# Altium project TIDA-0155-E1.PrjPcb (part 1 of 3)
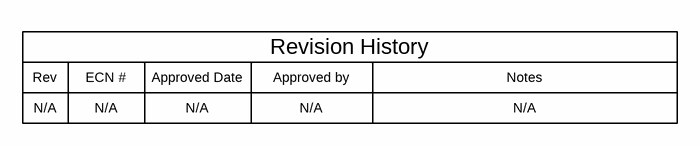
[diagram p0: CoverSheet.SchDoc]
CopyrightYear: 2017; PCB_Layout: Prasanna Rajagopal; PCB_Rev: E1; PRJ_Customer: Public Release; PRJ_Engineer: Prasanna Rajagopal; PRJ_Number: TIDA-01555; PRJ_Title: Enhanced Interface Reference Design to Connect Multiple ADCs to Processor for Input Expansion (48ch); SCH_Rev: E1; TechSupport: http://www.ti.com/support; TID: 01555
10 sheets, 765 parts. Net scope: global (net labels, ports and power ports of the same name join across sheets).
Board file: PCB.PcbDoc
Sheets:
  CoverSheet.SchDoc
  BlankSheet.SchDoc
  EVM_Hardware.SchDoc
  Page1.SchDoc
  Page2.SchDoc
  Page3.SchDoc
  Page4.SchDoc
  Page5.SchDoc
  Page6.SchDoc
  Paget2.SchDoc

## Sheet CoverSheet.SchDoc
size 431 x 279 mm; Date: Not shown in title block; ApprovedBy: Not shown in title block; CheckedBy: Not shown in title block; Author: Not shown in title block; CompanyName: Not shown in title block; Engineer: Not shown in title block; Organization: Not shown in title block; Address1: Not shown in title block; Address2: Not shown in title block; Address3: Not shown in title block; Address4: Not shown in title block; DocumentNumber: 1; Revision: Use project parameter SCH_Rev; SheetNumber: 1; SheetTotal: 3; PageSetup: Record=PageOptions¦CenterHorizontal=True¦CenterVertical=True¦PrintScale=1.00¦XCorrection=1.00¦YCorrection=1.00¦PrintKind=0¦BorderSize=5000000¦LeftOffset=0¦BottomOffset=0¦Orientation=2¦PaperLength=1000¦PaperWidth=1000¦Scale=100¦PaperSource=15¦PrintQuality=600¦MediaType=1¦DitherType=10¦PaperKind=Letter¦PrintScaleMode=1

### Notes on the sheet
- Rev
- N/A
- ECN #
- Approved Date
- Approved by
- Revision History
- Notes

## Sheet BlankSheet.SchDoc
size 431 x 279 mm; Date: Not shown in title block; ApprovedBy: Not shown in title block; CheckedBy: Not shown in title block; Author: Not shown in title block; CompanyName: Not shown in title block; Engineer: Not shown in title block; Organization: Not shown in title block; Address1: Not shown in title block; Address2: Not shown in title block; Address3: Not shown in title block; Address4: Not shown in title block; DocumentNumber: 1; Revision: Use project parameter SCH_Rev; SheetNumber: 2; SheetTotal: 3; PageSetup: Record=PageOptions¦CenterHorizontal=True¦CenterVertical=True¦PrintScale=1.00¦XCorrection=1.00¦YCorrection=1.00¦PrintKind=0¦BorderSize=5000000¦LeftOffset=0¦BottomOffset=0¦Orientation=2¦PaperLength=1000¦PaperWidth=1000¦Scale=100¦PaperSource=15¦PrintQuality=600¦MediaType=1¦DitherType=10¦PaperKind=Letter¦PrintScaleMode=1

## Sheet EVM_Hardware.SchDoc
size 431 x 279 mm; Date: Not shown in title block; ApprovedBy: Not shown in title block; CheckedBy: Not shown in title block; Author: Not shown in title block; CompanyName: Not shown in title block; Engineer: Not shown in title block; Organization: Not shown in title block; Address1: Not shown in title block; Address2: Not shown in title block; Address3: Not shown in title block; Address4: Not shown in title block; DocumentNumber: 1; Revision: Use project parameter SCH_Rev; SheetNumber: 3; SheetTotal: 3; PageSetup: Record=PageOptions¦CenterHorizontal=True¦CenterVertical=True¦PrintScale=1.00¦XCorrection=1.00¦YCorrection=1.00¦PrintKind=0¦BorderSize=5000000¦LeftOffset=0¦BottomOffset=0¦Orientation=2¦PaperLength=1000¦PaperWidth=1000¦Scale=100¦PaperSource=15¦PrintQuality=600¦MediaType=1¦DitherType=10¦PaperKind=Letter¦PrintScaleMode=1
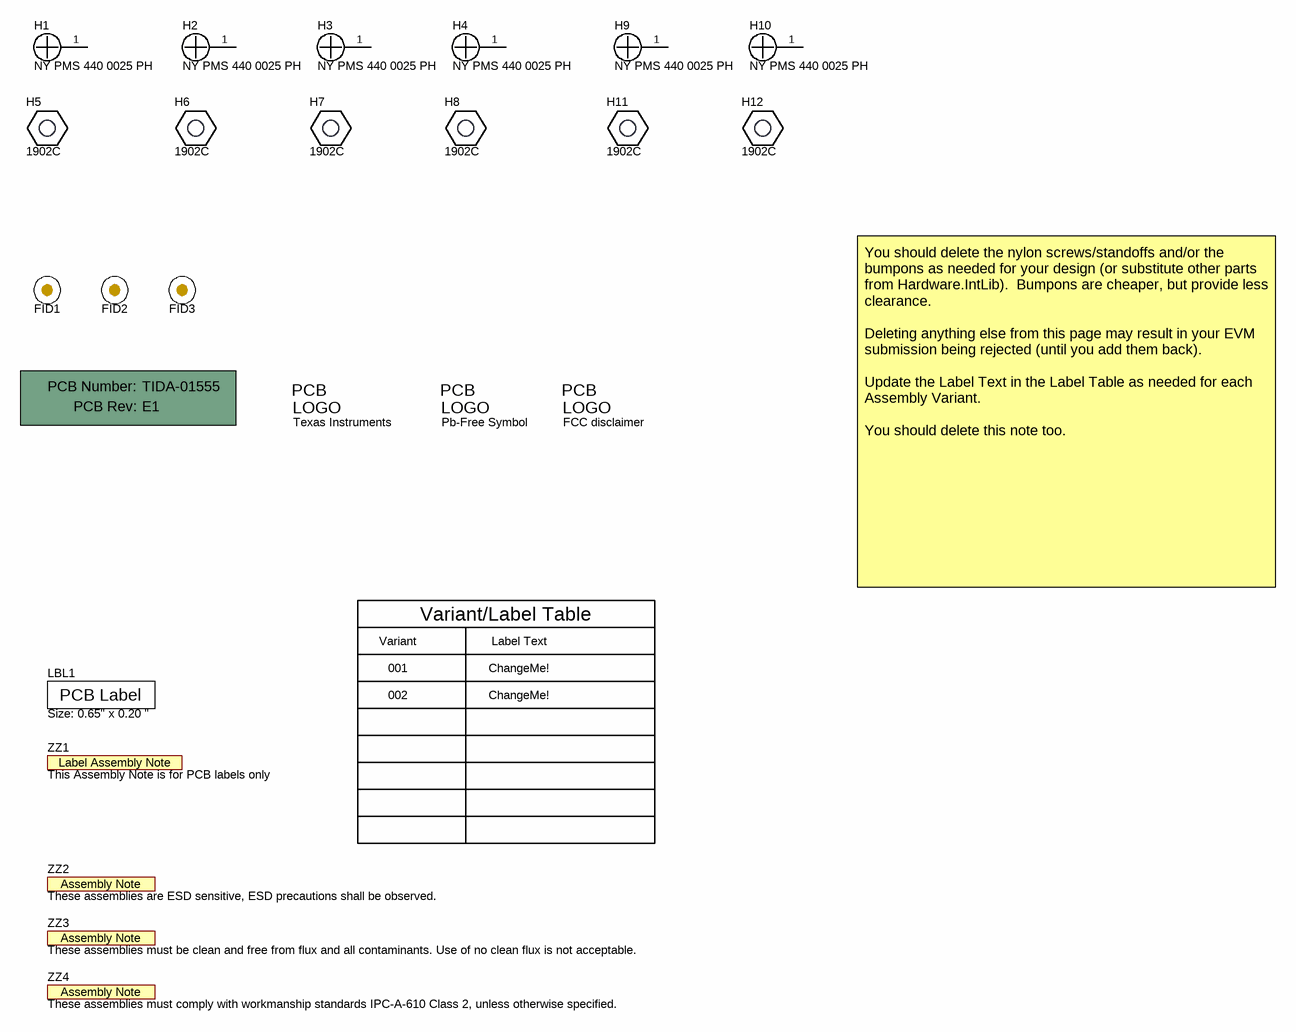
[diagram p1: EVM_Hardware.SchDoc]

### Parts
!PCB1  Printed Circuit Board  (value not drawn)  (mechanical)
FID1  Fiducial  [Fiducial10-20]  (value not drawn)
FID2  Fiducial  [Fiducial10-20]  (value not drawn)
FID3  Fiducial  [Fiducial10-20]  (value not drawn)
H1  NY PMS 440 0025 PH  [NY PMS 440 0025 PH]
H2  NY PMS 440 0025 PH  [NY PMS 440 0025 PH]
H3  NY PMS 440 0025 PH  [NY PMS 440 0025 PH]
H4  NY PMS 440 0025 PH  [NY PMS 440 0025 PH]
H5  1902C  [Keystone_1902C]
H6  1902C  [Keystone_1902C]
H7  1902C  [Keystone_1902C]
H8  1902C  [Keystone_1902C]
H9  NY PMS 440 0025 PH  [NY PMS 440 0025 PH]
H10  NY PMS 440 0025 PH  [NY PMS 440 0025 PH]
H11  1902C  [Keystone_1902C]
H12  1902C  [Keystone_1902C]
LBL1  Size: 0.65" x 0.20 "  [Label_650x200]
Logo1  Texas Instruments  [TI_Stacked_Overlay_Small]  (no BOM)
Logo2  Pb-Free Symbol  [Pb-Free_Overlay_Small]  (no BOM)
Logo3  FCC disclaimer  [FCC_disclaimer]  (no BOM)
ZZ1  This Assembly Note is for PCB labels only  [AssemblyNoteLabel]  (no BOM)
ZZ2  These assemblies are ESD sensitive, ESD precautions shall be observed.  [AssemblyNote]  (no BOM)
ZZ3  These assemblies must be clean and free from flux and all contaminants. Use of no clean flux is not acceptable.  [AssemblyNote]  (no BOM)
ZZ4  These assemblies must comply with workmanship standards IPC-A-610 Class 2, unless otherwise specified.  [AssemblyNote]  (no BOM)

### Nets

Not connected (* = marked no-connect by the designer): H1 1; H2 1; H3 1; H4 1; H9 1; H10 1

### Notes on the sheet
- Variant
- Variant/Label Table
- Label Text
- You should delete the nylon screws/standoffs and/or the bumpons as needed for your design (or substitute other parts from Hardware.IntLib).  Bumpons are cheaper, but provide less clearance.
  Deleting anything else from this page may result in your EVM submission being rejected (until you add them back).
  Update the Label Text in the Label Table as needed for each Assembly Variant.
  You should delete this note too.
- 001
- 002
- ChangeMe!

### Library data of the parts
!PCB1 = PCB: Manufacturer: Any; PartNumber: TIDA-01555; SymbolCreator: a0412235
FID1-FID3 = Fiducial: Fiducial mark.  There is nothing to buy or mount.; SymbolCreator: codlsc
H1-H4 H9 H10 = NY PMS 440 0025 PH: Machine Screw, Round, #4-40 x 1/4, Nylon, Philips panhead; Manufacturer: B&F Fastener Supply; CompType: Hardware; SymbolCreator: codlsc; U/M: EA
H5-H8 H11 H12 = 1902C: Standoff, Hex, 0.5"L #4-40 Nylon; Manufacturer: Keystone; CompType: Hardware
LBL1 = THT-14-423-10: Thermal Transfer Printable Labels, 0.650" W x 0.200" H - 10,000 per roll; Manufacturer: Brady; SymbolCreator: a0412235; CompType: Label
Logo1 = TI_Logo: Texas Instrument Corporate Signature; SymbolCreator: codlsc
Logo2 = Pb-Free: SymbolCreator: a0412235
Logo3 = FCC_disclaimer: SymbolCreator: codlsc
ZZ1 = AssemblyNoteLabel: SymbolCreator: a0412235
ZZ2-ZZ4 = AssemblyNote: SymbolCreator: codlsc

## Sheet Page1.SchDoc
size 431 x 279 mm; Date: Not shown in title block; ApprovedBy: Not shown in title block; CheckedBy: Not shown in title block; Author: Not shown in title block; CompanyName: Not shown in title block; Engineer: Not shown in title block; Organization: Not shown in title block; Address1: Not shown in title block; Address2: Not shown in title block; Address3: Not shown in title block; Address4: Not shown in title block; DocumentNumber: 1; Revision: Use project parameter SCH_Rev; SheetNumber: 2; SheetTotal: 3; PageSetup: Record=PageOptions¦CenterHorizontal=True¦CenterVertical=True¦PrintScale=1.00¦XCorrection=1.00¦YCorrection=1.00¦PrintKind=0¦BorderSize=5000000¦LeftOffset=0¦BottomOffset=0¦Orientation=2¦PaperLength=1000¦PaperWidth=1000¦Scale=100¦PaperSource=15¦PrintQuality=600¦MediaType=1¦DitherType=10¦PaperKind=Letter¦PrintScaleMode=1
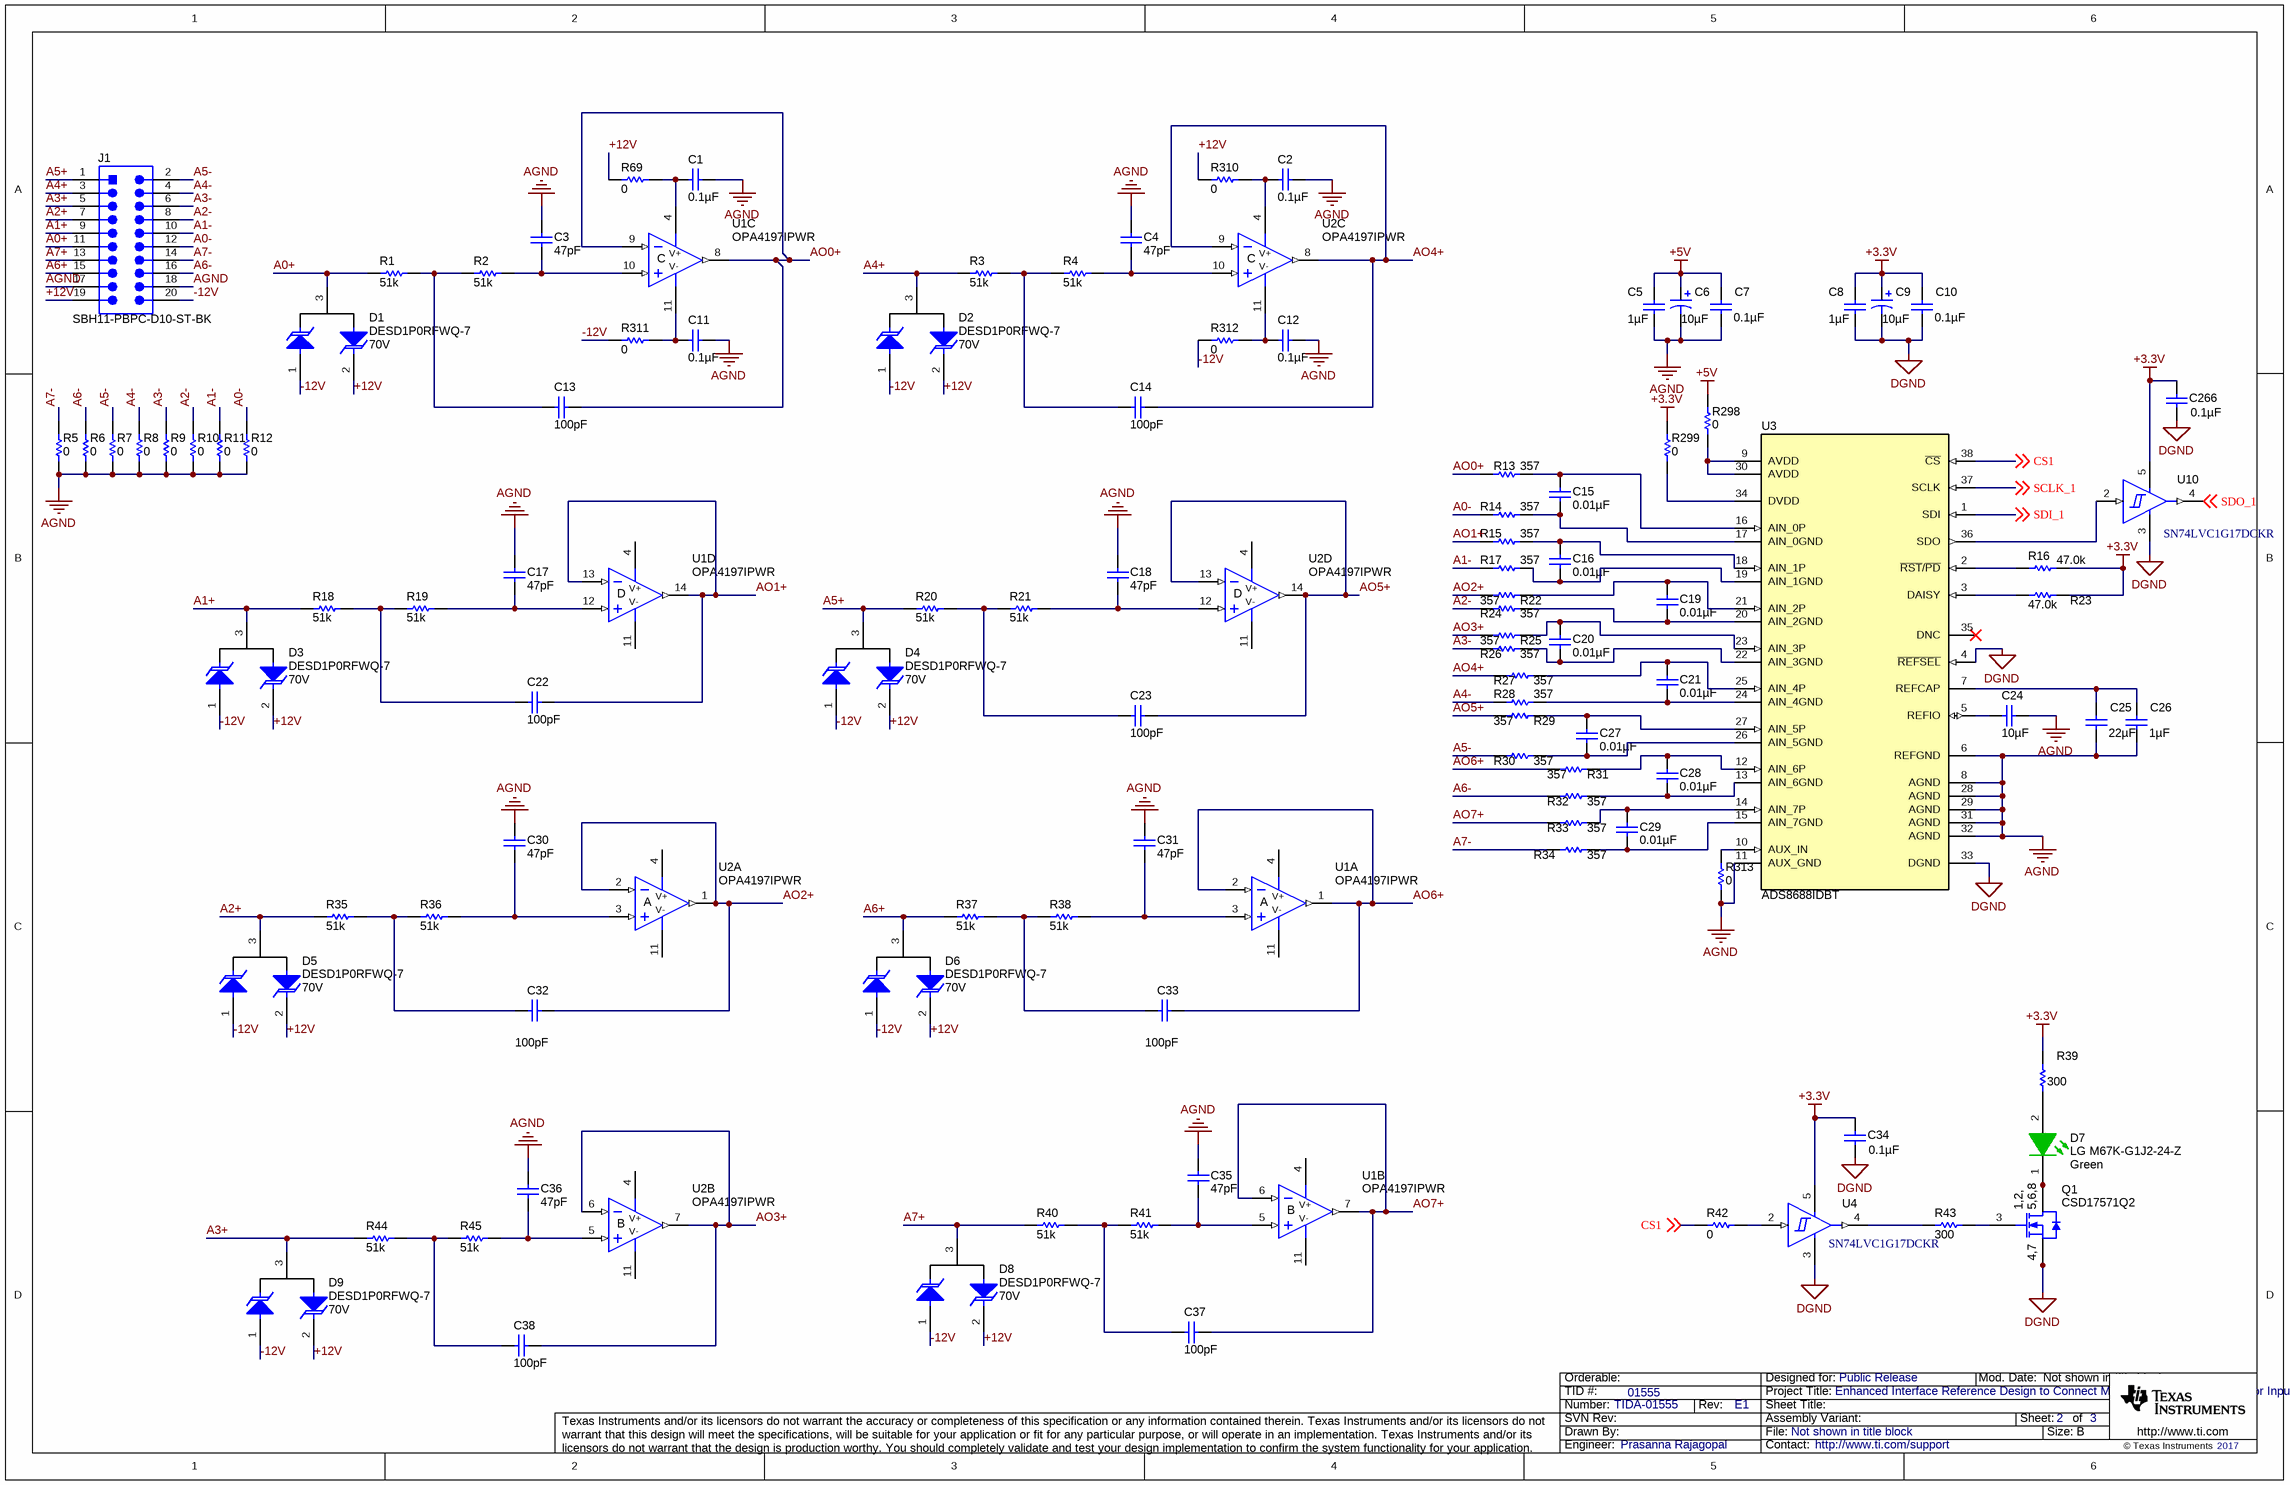
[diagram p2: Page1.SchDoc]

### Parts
C1  ValueDisplayed: 0.1µF  [0603]  (hidden comment: 06035C104KAT2A)
C2  ValueDisplayed: 0.1µF  [0603]  (hidden comment: 06035C104KAT2A)
C3  ValueDisplayed: 47pF  [0603]  (hidden comment: C0603C470J5GACTU)
C4  ValueDisplayed: 47pF  [0603]  (hidden comment: C0603C470J5GACTU)
C5  ValueDisplayed: 1µF  [0805_HV]  (hidden comment: LMK212B7105KD-T)
C6  ValueDisplayed: 10µF  [3216-18]  (hidden comment: TAJA106M010RNJ)
C7  ValueDisplayed: 0.1µF  [0402]  (hidden comment: C1005X5R1A104K050BA)
C8  ValueDisplayed: 1µF  [0805_HV]  (hidden comment: LMK212B7105KD-T)
C9  ValueDisplayed: 10µF  [3216-18]  (hidden comment: TAJA106M010RNJ)
C10  ValueDisplayed: 0.1µF  [0402]  (hidden comment: C1005X5R1A104K050BA)
C11  ValueDisplayed: 0.1µF  [0603]  (hidden comment: 06035C104KAT2A)
C12  ValueDisplayed: 0.1µF  [0603]  (hidden comment: 06035C104KAT2A)
C13  ValueDisplayed: 100pF  [0603]  (hidden comment: 06035A101FAT2A)
C14  ValueDisplayed: 100pF  [0603]  (hidden comment: 06035A101FAT2A)
C15  ValueDisplayed: 0.01µF  [0603]  (hidden comment: C1608X7R1H103K080AA)
C16  ValueDisplayed: 0.01µF  [0603]  (hidden comment: C1608X7R1H103K080AA)
C17  ValueDisplayed: 47pF  [0603]  (hidden comment: C0603C470J5GACTU)
C18  ValueDisplayed: 47pF  [0603]  (hidden comment: C0603C470J5GACTU)
C19  ValueDisplayed: 0.01µF  [0603]  (hidden comment: C1608X7R1H103K080AA)
C20  ValueDisplayed: 0.01µF  [0603]  (hidden comment: C1608X7R1H103K080AA)
C21  ValueDisplayed: 0.01µF  [0603]  (hidden comment: C1608X7R1H103K080AA)
C22  ValueDisplayed: 100pF  [0603]  (hidden comment: 06035A101FAT2A)
C23  ValueDisplayed: 100pF  [0603]  (hidden comment: 06035A101FAT2A)
C24  ValueDisplayed: 10µF  [0805_HV]  (hidden comment: GRM21BR71A106KE51L)
C25  ValueDisplayed: 22µF  [1210_280]  (hidden comment: C3225X7R1C226K250AC)
C26  ValueDisplayed: 1µF  [0603]  (hidden comment: C1608X7R1C105K080AC)
C27  ValueDisplayed: 0.01µF  [0603]  (hidden comment: C1608X7R1H103K080AA)
C28  ValueDisplayed: 0.01µF  [0603]  (hidden comment: C1608X7R1H103K080AA)
C29  ValueDisplayed: 0.01µF  [0603]  (hidden comment: C1608X7R1H103K080AA)
C30  ValueDisplayed: 47pF  [0603]  (hidden comment: C0603C470J5GACTU)
C31  ValueDisplayed: 47pF  [0603]  (hidden comment: C0603C470J5GACTU)
C32  ValueDisplayed: 100pF  [0603]  (hidden comment: 06035A101FAT2A)
C33  ValueDisplayed: 100pF  [0603]  (hidden comment: 06035A101FAT2A)
C34  ValueDisplayed: 0.1µF  [0603]  (hidden comment: GRM188R71C104KA01D)
C35  ValueDisplayed: 47pF  [0603]  (hidden comment: C0603C470J5GACTU)
C36  ValueDisplayed: 47pF  [0603]  (hidden comment: C0603C470J5GACTU)
C37  ValueDisplayed: 100pF  [0603]  (hidden comment: 06035A101FAT2A)
C38  ValueDisplayed: 100pF  [0603]  (hidden comment: 06035A101FAT2A)
C266  ValueDisplayed: 0.1µF  [0603]  (hidden comment: GRM188R71C104KA01D)
D1  DESD1P0RFWQ-7  value 70V  [SOT-323]
D2  DESD1P0RFWQ-7  value 70V  [SOT-323]
D3  DESD1P0RFWQ-7  value 70V  [SOT-323]
D4  DESD1P0RFWQ-7  value 70V  [SOT-323]
D5  DESD1P0RFWQ-7  value 70V  [SOT-323]
D6  DESD1P0RFWQ-7  value 70V  [SOT-323]
D7  LG M67K-G1J2-24-Z  value Green  [LG_M67K_Green]
D8  DESD1P0RFWQ-7  value 70V  [SOT-323]
D9  DESD1P0RFWQ-7  value 70V  [SOT-323]
J1  SBH11-PBPC-D10-ST-BK  [Sullins_SBH11-xxxC-D10-ST]
Q1  CSD17571Q2  [DQK0006C]
R1  ValueDisplayed: 51k  [0603]  (hidden comment: CRCW060351K0JNEA)
R2  ValueDisplayed: 51k  [0603]  (hidden comment: CRCW060351K0JNEA)
R3  ValueDisplayed: 51k  [0603]  (hidden comment: CRCW060351K0JNEA)
R4  ValueDisplayed: 51k  [0603]  (hidden comment: CRCW060351K0JNEA)
R5  ValueDisplayed: 0  [0603]  (hidden comment: CRCW06030000Z0EA)
R6  ValueDisplayed: 0  [0603]  (hidden comment: CRCW06030000Z0EA)
R7  ValueDisplayed: 0  [0603]  (hidden comment: CRCW06030000Z0EA)
R8  ValueDisplayed: 0  [0603]  (hidden comment: CRCW06030000Z0EA)
R9  ValueDisplayed: 0  [0603]  (hidden comment: CRCW06030000Z0EA)
R10  ValueDisplayed: 0  [0603]  (hidden comment: CRCW06030000Z0EA)
R11  ValueDisplayed: 0  [0603]  (hidden comment: CRCW06030000Z0EA)
R12  ValueDisplayed: 0  [0603]  (hidden comment: CRCW06030000Z0EA)
R13  ValueDisplayed: 357  [0402]  (hidden comment: CRCW0402357RFKED)
R14  ValueDisplayed: 357  [0402]  (hidden comment: CRCW0402357RFKED)
R15  ValueDisplayed: 357  [0402]  (hidden comment: CRCW0402357RFKED)
R16  ValueDisplayed: 47.0k  [0603]  (hidden comment: RC0603FR-0747KL)
R17  ValueDisplayed: 357  [0402]  (hidden comment: CRCW0402357RFKED)
R18  ValueDisplayed: 51k  [0603]  (hidden comment: CRCW060351K0JNEA)
R19  ValueDisplayed: 51k  [0603]  (hidden comment: CRCW060351K0JNEA)
R20  ValueDisplayed: 51k  [0603]  (hidden comment: CRCW060351K0JNEA)
R21  ValueDisplayed: 51k  [0603]  (hidden comment: CRCW060351K0JNEA)
R22  ValueDisplayed: 357  [0402]  (hidden comment: CRCW0402357RFKED)
R23  ValueDisplayed: 47.0k  [0603]  (hidden comment: RC0603FR-0747KL)
R24  ValueDisplayed: 357  [0402]  (hidden comment: CRCW0402357RFKED)
R25  ValueDisplayed: 357  [0402]  (hidden comment: CRCW0402357RFKED)
R26  ValueDisplayed: 357  [0402]  (hidden comment: CRCW0402357RFKED)
R27  ValueDisplayed: 357  [0402]  (hidden comment: CRCW0402357RFKED)
R28  ValueDisplayed: 357  [0402]  (hidden comment: CRCW0402357RFKED)
R29  ValueDisplayed: 357  [0402]  (hidden comment: CRCW0402357RFKED)
R30  ValueDisplayed: 357  [0402]  (hidden comment: CRCW0402357RFKED)
R31  ValueDisplayed: 357  [0402]  (hidden comment: CRCW0402357RFKED)
R32  ValueDisplayed: 357  [0402]  (hidden comment: CRCW0402357RFKED)
R33  ValueDisplayed: 357  [0402]  (hidden comment: CRCW0402357RFKED)
R34  ValueDisplayed: 357  [0402]  (hidden comment: CRCW0402357RFKED)
R35  ValueDisplayed: 51k  [0603]  (hidden comment: CRCW060351K0JNEA)
R36  ValueDisplayed: 51k  [0603]  (hidden comment: CRCW060351K0JNEA)
R37  ValueDisplayed: 51k  [0603]  (hidden comment: CRCW060351K0JNEA)
R38  ValueDisplayed: 51k  [0603]  (hidden comment: CRCW060351K0JNEA)
R39  ValueDisplayed: 300  [0603]  (hidden comment: CRCW0603300RJNEA)
R40  ValueDisplayed: 51k  [0603]  (hidden comment: CRCW060351K0JNEA)
R41  ValueDisplayed: 51k  [0603]  (hidden comment: CRCW060351K0JNEA)
R42  ValueDisplayed: 0  [0603]  (hidden comment: RMCF0603ZT0R00)
R43  ValueDisplayed: 300  [0603]  (hidden comment: CRCW0603300RJNEA)
R44  ValueDisplayed: 51k  [0603]  (hidden comment: CRCW060351K0JNEA)
R45  ValueDisplayed: 51k  [0603]  (hidden comment: CRCW060351K0JNEA)
R69  ValueDisplayed: 0  [0402]  (hidden comment: CRCW04020000Z0ED)
R298  ValueDisplayed: 0  [0603]  (hidden comment: CRCW06030000Z0EA)
R299  ValueDisplayed: 0  [0603]  (hidden comment: CRCW06030000Z0EA)
R310  ValueDisplayed: 0  [0402]  (hidden comment: CRCW04020000Z0ED)
R311  ValueDisplayed: 0  [0402]  (hidden comment: CRCW04020000Z0ED)
R312  ValueDisplayed: 0  [0402]  (hidden comment: CRCW04020000Z0ED)
R313  ValueDisplayed: 0  [0402]  (hidden comment: CRCW04020000Z0ED)
U1  OPA4197IPWR  [PW0014A_N]  (parts A,B,C,D of 4)
U2  OPA4197IPWR  [PW0014A_N]  (parts A,B,C,D of 4)
U3  ADS8688IDBT  [DBT0038A_N]
U4  SN74LVC1G17DCKR  [DCK0005A_N]
U10  SN74LVC1G17DCKR  [DCK0005A_N]

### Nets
+3.3V: C8.1 C9.1(+) C10.1 C34.1 C266.1 R16.2 R23.2 R39.2 R299.2 U4.5(VCC) U10.5(VCC)
+5V: C5.1 C6.1(+) C7.1 R298.2
+12V: D1.2(C) D2.2(C) D3.2(C) D4.2(C) D5.2(C) D6.2(C) D8.2(C) D9.2(C) J1.19 R69.1 R310.1
-12V: D1.1(A) D2.1(A) D3.1(A) D4.1(A) D5.1(A) D6.1(A) D8.1(A) D9.1(A) J1.20 R311.1 R312.1
AGND: C1.1 C2.1 C3.1 C4.1 C5.2 C6.2(-) C7.2 C11.1 C12.1 C17.1 C18.1 C24.2 C25.2 C26.2 C30.1 C31.1 C35.1 C36.1 J1.17 J1.18 R5.1 R6.1 R7.1 R8.1 R9.1 R10.1 R11.1 R12.1 R313.1 U3.6(REFGND) U3.8(AGND) U3.11(AUX_GND) U3.28(AGND) U3.29(AGND) U3.31(AGND) U3.32(AGND)
DGND: C8.2 C9.2(-) C10.2 C34.2 C266.2 Q1.4(S) Q1.7(S) U3.4(~{REFSEL}) U3.33(DGND) U4.3(GND) U10.3(GND)
A0+: D1.3(C) J1.11 R1.1
A0-: J1.12 R12.2 R14.1
A1+: D3.3(C) J1.9 R18.1
A1-: J1.10 R11.2 R17.1
A2+: D5.3(C) J1.7 R35.1
A2-: J1.8 R10.2 R24.1
A3+: D9.3(C) J1.5 R44.1
A3-: J1.6 R9.2 R26.1
A4+: D2.3(C) J1.3 R3.1
A4-: J1.4 R8.2 R28.1
A5+: D4.3(C) J1.1 R20.1
A5-: J1.2 R7.2 R30.1
A6+: D6.3(C) J1.15 R37.1
A6-: J1.16 R6.2 R32.1
A7+: D8.3(C) J1.13 R40.1
A7-: J1.14 R5.2 R34.1
AO0+: C13.1 R13.1 U1.8(OUT) U1.9(IN-)
AO1+: C22.1 R15.1 U1.13(IN-) U1.14(OUT)
AO2+: C32.1 R22.1 U2.1(OUT) U2.2(IN-)
AO3+: C38.1 R25.1 U2.6(IN-) U2.7(OUT)
AO4+: C14.1 R27.1 U2.8(OUT) U2.9(IN-)
AO5+: C23.1 R29.1 U2.13(IN-) U2.14(OUT)
AO6+: C33.1 R31.1 U1.1(OUT) U1.2(IN-)
AO7+: C37.1 R33.1 U1.6(IN-) U1.7(OUT)
CS1: R42.1 U3.38(~{CS}) ; off-sheet CS1
SCLK_1: U3.37(SCLK) ; off-sheet SCLK_1
SDI_1: U3.1(SDI) ; off-sheet SDI_1
SDO_1: U10.4(Y) ; off-sheet SDO_1
NetC1_2: C1.2 R69.2 U1.4(V+)
NetC2_2: C2.2 R310.2 U2.4(V+)
NetC3_2: C3.2 R2.2 U1.10(IN+)
NetC4_2: C4.2 R4.2 U2.10(IN+)
NetC11_2: C11.2 R311.2 U1.11(V-)
NetC12_2: C12.2 R312.2 U2.11(V-)
NetC13_2: C13.2 R1.2 R2.1
NetC14_2: C14.2 R3.2 R4.1
NetC15_1: C15.1 R13.2 U3.16(AIN_0P)
NetC15_2: C15.2 R14.2 U3.17(AIN_0GND)
NetC16_1: C16.1 R15.2 U3.18(AIN_1P)
NetC16_2: C16.2 R17.2 U3.19(AIN_1GND)
NetC17_2: C17.2 R19.2 U1.12(IN+)
NetC18_2: C18.2 R21.2 U2.12(IN+)
NetC19_1: C19.1 R22.2 U3.21(AIN_2P)
NetC19_2: C19.2 R24.2 U3.20(AIN_2GND)
NetC20_1: C20.1 R25.2 U3.23(AIN_3P)
NetC20_2: C20.2 R26.2 U3.22(AIN_3GND)
NetC21_1: C21.1 R27.2 U3.25(AIN_4P)
NetC21_2: C21.2 R28.2 U3.24(AIN_4GND)
NetC22_2: C22.2 R18.2 R19.1
NetC23_2: C23.2 R20.2 R21.1
NetC24_1: C24.1 U3.5(REFIO)
NetC25_1: C25.1 C26.1 U3.7(REFCAP)
NetC27_1: C27.1 R29.2 U3.27(AIN_5P)
NetC27_2: C27.2 R30.2 U3.26(AIN_5GND)
NetC28_1: C28.1 R31.2 U3.12(AIN_6P)
NetC28_2: C28.2 R32.2 U3.13(AIN_6GND)
NetC29_1: C29.1 R33.2 U3.14(AIN_7P)
NetC29_2: C29.2 R34.2 U3.15(AIN_7GND)
NetC30_2: C30.2 R36.2 U2.3(IN+)
NetC31_2: C31.2 R38.2 U1.3(IN+)
NetC32_2: C32.2 R35.2 R36.1
NetC33_2: C33.2 R37.2 R38.1
NetC35_2: C35.2 R41.2 U1.5(IN+)
NetC36_2: C36.2 R45.2 U2.5(IN+)
NetC37_2: C37.2 R40.2 R41.1
NetC38_2: C38.2 R44.2 R45.1
NetD7_1: D7.1(K) Q1.1(D) Q1.2(D) Q1.5(D) Q1.6(D) Q1.8(D)
NetD7_2: D7.2(A) R39.1
NetQ1_3: Q1.3(G) R43.1
NetR16_1: R16.1 U3.2(~{RST}/~{PD})
NetR23_1: R23.1 U3.3(DAISY)
NetR42_2: R42.2 U4.2(A)
NetR43_2: R43.2 U4.4(Y)
NetR298_1: R298.1 U3.9(AVDD) U3.30(AVDD)
NetR299_1: R299.1 U3.34(DVDD)
NetR313_2: R313.2 U3.10(AUX_IN)
NetU3_36: U3.36(SDO) U10.2(A)

Not connected (* = marked no-connect by the designer): U3 35(DNC)*

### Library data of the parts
C1 C2 C11 C12 = 06035C104KAT2A: CAP, CERM, 0.1 µF, 50 V,+/- 10%, X7R, 0603; Manufacturer: AVX; Polarized: N; CompType: Capacitor; Value: 0.1uF; U/M: EA; Cap_F: 0.0000001; Tolerance_%: 10; VDC_V: 50; Value2: 50V; TaMin_C: -55; TaMax_C: 125; SizeArea_mm2: 1.28; SizeAreaWB_mm2: 4.68; SizeX_mm: 1.6; SizeY_mm: 0.8; SizeZ_mm: 1; AEC Category: Q200; Green_Lifecycle: Active; Green_REACh: Passed
C3 C4 C17 C18 C30 C31 C35 C36 = C0603C470J5GACTU: CAP, CERM, 47 pF, 50 V,+/- 5%, C0G/NP0, 0603; Manufacturer: Kemet; Polarized: N; CompType: Capacitor; Value: 47pF; U/M: EA; Cap_F: 0.000000000047; Tolerance_%: 5; VDC_V: 50; Value2: 50V; TaMin_C: -55; TaMax_C: 125; SizeArea_mm2: 1.28; SizeAreaWB_mm2: 4.68; SizeX_mm: 1.6; SizeY_mm: 0.8; SizeZ_mm: 1; AEC Category: Q200; Green_Lifecycle: Active; Green_REACh: Passed
C5 C8 = LMK212B7105KD-T: CAP, CERM, 1 µF, 10 V, +/- 10%, X7R, 0805; Manufacturer: Taiyo Yuden; Polarized: N; CompType: Capacitor; Value: 1uF; U/M: EA; Cap_F: 0.000001; Tolerance_%: 10; Value1: Unknown; Value2: 10V; TaMin_C: -55; TaMax_C: 125; Cap_Case: 0805; SizeArea_mm2: 2.5; SizeAreaWB_mm2: 6.75; SizeX_mm: 2; SizeY_mm: 1.25; SizeZ_mm: 1.45; AEC Category: Q200
C6 C9 = TAJA106M010RNJ: CAP, TA, 10 µF, 10 V, +/- 20%, 3 ohm, SMD; Manufacturer: AVX; Polarized: Y; CompType: Capacitor; Value: 10uF; U/M: EA; Cap_F: 0.00001; Tolerance_%: 20; Value1: 3 ohm; VDC_V: 10; Value2: 10V; ESR_ohm: 3; TaMin_C: -55; TaMax_C: 125; SizeAreaWB_mm2: 10.92; SizeArea_mm2: 5.12; SizeX_mm: 3.2; SizeY_mm: 1.6; SizeZ_mm: 1.8; AEC Category: Q200
C7 C10 = C1005X5R1A104K050BA: CAP, CERM, 0.1 µF, 10 V, +/- 10%, X5R, 0402; Manufacturer: TDK; Polarized: N; CompType: Capacitor; Value: 0.1uF; U/M: EA; Cap_F: 0.0000001; Tolerance_%: 10; Value1: Unknown; Value2: 10V; TaMin_C: -55; TaMax_C: 85; SizeArea_mm2: 0.5; SizeAreaWB_mm2: 3; SizeX_mm: 1; SizeZ_mm: 0.6; AEC Category: Q200
C13 C14 C22 C23 C32 C33 C37 C38 = 06035A101FAT2A: CAP, CERM, 100 pF, 50 V,+/- 1%, C0G/NP0, 0603; Manufacturer: AVX; Polarized: N; CompType: Capacitor; Value: 100pF; U/M: EA; Cap_F: 0.0000000001; Tolerance_%: 1; VDC_V: 50; Value2: 50V; TaMin_C: -55; TaMax_C: 125; SizeArea_mm2: 1.28; SizeAreaWB_mm2: 4.68; SizeX_mm: 1.6; SizeY_mm: 0.8; AEC Category: Q200; Green_Lifecycle: Active; Green_REACh: Passed
C15 C16 C19-C21 C27-C29 = C1608X7R1H103K080AA: CAP, CERM, 0.01 µF, 50 V,+/- 10%, X7R, 0603; Manufacturer: TDK; Polarized: N; CompType: Capacitor; Value: 0.01uF; U/M: EA; Cap_F: 0.00000001; Tolerance_%: 10; ESR_ohm: 0.0539; Value1: 0.0539 ohm; VDC_V: 50; Value2: 50V; TaMin_C: -55; TaMax_C: 125; SizeArea_mm2: 1.28; SizeAreaWB_mm2: 4.68; SizeX_mm: 1.6; SizeY_mm: 0.8; SizeZ_mm: 1; AEC Category: Q200; Green_Lifecycle: NRND; Green_REACh: Passed
C24 = GRM21BR71A106KE51L: CAP, CERM, 10 µF, 10 V,+/- 10%, X7R, 0805; Manufacturer: MuRata; Polarized: N; CompType: Capacitor; Value: 10uF; U/M: EA; Cap_F: 0.00001; Tolerance_%: 10; ESR_ohm: 0.003; Value1: 0.003 ohm; Value2: 10V; TaMin_C: -55; TaMax_C: 125; Cap_Case: 0805; SizeArea_mm2: 2.5; SizeAreaWB_mm2: 6.75; SizeX_mm: 2; SizeY_mm: 1.25; SizeZ_mm: 1.45; AEC Category: Q200; Green_Lifecycle: Active; Green_REACh: Passed
C25 = C3225X7R1C226K250AC: CAP, CERM, 22 µF, 16 V,+/- 10%, X7R, 1210; Manufacturer: TDK; Polarized: N; CompType: Capacitor; Value: 22uF; U/M: EA; Cap_F: 0.000022; Tolerance_%: 10; ESR_ohm: 0.002582; Value1: 0.002582 ohm; VDC_V: 16; Value2: 16V; IRMS_A: 4.57562; TaMin_C: -55; TaMax_C: 125; Cap_Case: 1210; SizeArea_mm2: 8; SizeAreaWB_mm2: 14.7; SizeX_mm: 3.2; SizeY_mm: 2.5; SizeZ_mm: 2.8; AEC Category: Q200; Green_Lifecycle: Active; Green_REACh: Passed
C26 = C1608X7R1C105K080AC: CAP, CERM, 1 µF, 16 V,+/- 10%, X7R, 0603; Manufacturer: TDK; Polarized: N; CompType: Capacitor; Value: 1uF; U/M: EA; Cap_F: 0.000001; Tolerance_%: 10; ESR_ohm: 0.0057; Value1: 0.0057 ohm; VDC_V: 16; Value2: 16V; TaMin_C: -55; TaMax_C: 125; SizeArea_mm2: 1.28; SizeAreaWB_mm2: 4.68; SizeX_mm: 1.6; SizeY_mm: 0.8; SizeZ_mm: 1; AEC Category: Q200; Green_Lifecycle: Active; Green_REACh: Passed
C34 C266 = GRM188R71C104KA01D: CAP, CERM, 0.1 µF, 16 V, +/- 10%, X7R, 0603; Manufacturer: MuRata; Polarized: N; CompType: Capacitor; Value: 0.1uF; U/M: EA; Cap_F: 0.0000001; Tolerance_%: 10; Value1: Unknown; VDC_V: 16; Value2: 16V; TaMin_C: -55; TaMax_C: 125; SizeArea_mm2: 1.28; SizeAreaWB_mm2: 4.68; SizeX_mm: 1.6; SizeY_mm: 0.8; SizeZ_mm: 1; AEC Category: Q200
D1-D6 D8 D9 = DESD1P0RFWQ-7: Diode, TVS, Uni, 70 V, SOT-323; Manufacturer: Diodes Inc.; SymbolCreator: x0208325; U/M: EA; Power_W: 0.2; Vr_V: 70; Value1: 0.2W; SizeAreaWB_mm2: 10.24; SizeArea_mm2: 4.84; SizeX_mm: 2.2; SizeZ_mm: 1.1; AEC Category: Q101
D7 = LG M67K-G1J2-24-Z: LED, Green, SMD; Manufacturer: OSRAM; SymbolCreator: Altium; Type: AlInGaP; Vf_V: 1.8; Value2: 1.8V; Io_A: 0.002; Vr_V: 12; Tjmax_C: 125; Value1: W; Angle: 120; U/M: EA
J1 = SBH11-PBPC-D10-ST-BK: Header (Shrouded), 2.54mm, 10x2, Gold, Black, TH; Manufacturer: Sullins Connector Solutions; SymbolCreator: a0412235; Pitch_mm: 2.54; Gender: Male; Shrouded: Y; Row_Count: 2; Current_A: 3; Voltage_V: 1000; Green_Lifecycle: Not Set; Green_REACh: Incomplete
Q1 = CSD17571Q2: MOSFET, N-CH, 30 V, 22 A, DQK0006C (WSON-6); Manufacturer: Texas Instruments; Alternate Manufacturer: None; U/M: EA; ChType: N; Value: 30V; VdsMax_V: 30; Value1: 0.029 ohm; Rdson45_ohm: 0.029; Value2: 2.4 nC; QgTyp_nC: 2.4; Vgs_V: 20; IdsMax_A: 22; SizeAreaWB_mm2: 9; SizeArea_mm2: 4; SizeX_mm: 2; SizeZ_mm: 0.8; AEC Category: Q101
R1-R4 R18-R21 R35-R38 R40 R41 R44 R45 = CRCW060351K0JNEA: RES, 51 k, 5%, 0.1 W, 0603; Manufacturer: Vishay-Dale; CompType: Resistor; Value: 51k; Res_ohm: 51000; Value_Code: 51k0; Tolerance_%: 5; Power_W: 0.1; Value2: 0.1W; VDC_V: 75; TempCo: 200 ppm/C; SizeArea_mm2: 1.28; SizeX_mm: 1.6; SizeY_mm: 0.8; SizeZ_mm: 1; EIA_Code: E24; U/M: EA; AEC Category: Q200; Green_Lifecycle: Active; Green_REACh: Passed
R5-R12 R298 R299 = CRCW06030000Z0EA: RES, 0, 5%, 0.1 W, 0603; Manufacturer: Vishay-Dale; CompType: Resistor; Value: 0; Value_Code: 0000; Tolerance_%: 5; Power_W: 0.1; Value2: 0.1W; VDC_V: 75; TempCo: 200 ppm/C; EIA_Code: E24; U/M: EA
R13-R15 R17 R22 R24-R34 = CRCW0402357RFKED: RES, 357, 1%, 0.063 W, 0402; Manufacturer: Vishay-Dale; CompType: Resistor; Value: 357; Value_Code: 357R; Tolerance_%: 1; Power_W: 0.063; Value2: 0.063W; VDC_V: 50; TempCo: 100 ppm/C; SizeArea_mm2: 0.5; SizeZ_mm: 0.6; EIA_Code: E96; U/M: EA; AEC Category: Q200; Green_Lifecycle: Active; Green_REACh: Passed
R16 R23 = RC0603FR-0747KL: RES, 47.0 k, 1%, 0.1 W, 0603; Manufacturer: Yageo America; CompType: Resistor; Value: 47.0k; Res_ohm: 47000; Value_Code: 47k0; Tolerance_%: 1; Power_W: 0.1; Value2: 0.1W; VDC_V: 150; TempCo: 200 ppm/C; SizeArea_mm2: 1.28; SizeX_mm: 1.6; SizeY_mm: 0.8; U/M: EA; AEC Category: Q200; Green_Lifecycle: Active; Green_REACh: Passed
R39 R43 = CRCW0603300RJNEA: RES, 300, 5%, 0.1 W, 0603; Manufacturer: Vishay-Dale; CompType: Resistor; Value: 300; Value_Code: 300R; Tolerance_%: 5; Power_W: 0.1; Value2: 0.1W; VDC_V: 75; TempCo: 200 ppm/C; SizeArea_mm2: 1.28; SizeX_mm: 1.6; SizeY_mm: 0.8; SizeZ_mm: 1; EIA_Code: E24; U/M: EA; AEC Category: Q200
R42 = RMCF0603ZT0R00: RES, 0, 1%, 0.1 W, AEC-Q200 Grade 0, 0603; Manufacturer: Stackpole Electronics Inc; CompType: Resistor; Value: 0; Tolerance_%: 1; Power_W: 0.1; Value2: 0.1W; TempCo: ppm/C; SizeArea_mm2: 1.28; SizeX_mm: 1.6; SizeY_mm: 0.8; U/M: EA; AEC Category: Q200; AEC Qualified: Y
R69 R310-R313 = CRCW04020000Z0ED: RES, 0, 5%, 0.063 W, 0402; Manufacturer: Vishay-Dale; CompType: Resistor; Value: 0; Value_Code: 0000; Tolerance_%: 5; Power_W: 0.063; Value2: 0.063W; VDC_V: 50; TempCo: 200 ppm/C; EIA_Code: E24; U/M: EA; SizeArea_mm2: 0.5; SizeX_mm: 1; SizeZ_mm: 0.6; AEC Category: Q200; Green_Lifecycle: Active; Green_REACh: Passed
U1 U2 = OPA4197IPWR: 36-V, Precision, Rail-to-Rail Input Output, Low Offset Voltage Op Amp, PW0014A (TSSOP-14); Manufacturer: Texas Instruments; SymbolCreator: a0412235; SizeArea_mm2: 32; SizeAreaWB_mm2: 58.8; SizeX_mm: 6.4; SizeY_mm: 5; SizeZ_mm: 1.2; CompType: IC; U/M: EA
U3 = ADS8688IDBT: 16-Bit, 500-kSPS, 8-Channel, Single-Supply, SAR ADCs with Bipolar Input Ranges, DBT0038A (TSSOP-38); Manufacturer: Texas Instruments; SymbolCreator: Altium; SizeArea_mm2: 62.08; SizeAreaWB_mm2: 98.28; SizeX_mm: 6.4; SizeY_mm: 9.7; SizeZ_mm: 1.2; CompType: IC; U/M: EA
U4 U10 = SN74LVC1G17DCKR: SINGLE SCHMITT-TRIGGER BUFFER, DCK0005A (SOT-SC70-5); Alternate PartNumber: SN74LVC1G17DCKT; Manufacturer: Texas Instruments; SymbolCreator: a0799628; SizeArea_mm2: 4.2; SizeAreaWB_mm2: 9.3; SizeX_mm: 2.1; SizeY_mm: 2; SizeZ_mm: 1.1; CompType: IC; U/M: EA

## Sheet Page2.SchDoc
size 431 x 279 mm; Date: Not shown in title block; ApprovedBy: Not shown in title block; CheckedBy: Not shown in title block; Author: Not shown in title block; CompanyName: Not shown in title block; Engineer: Not shown in title block; Organization: Not shown in title block; Address1: Not shown in title block; Address2: Not shown in title block; Address3: Not shown in title block; Address4: Not shown in title block; DocumentNumber: 1; Revision: Use project parameter SCH_Rev; SheetNumber: 2; SheetTotal: 3; PageSetup: Record=PageOptions¦CenterHorizontal=True¦CenterVertical=True¦PrintScale=1.00¦XCorrection=1.00¦YCorrection=1.00¦PrintKind=0¦BorderSize=5000000¦LeftOffset=0¦BottomOffset=0¦Orientation=2¦PaperLength=1000¦PaperWidth=1000¦Scale=100¦PaperSource=15¦PrintQuality=600¦MediaType=1¦DitherType=10¦PaperKind=Letter¦PrintScaleMode=1
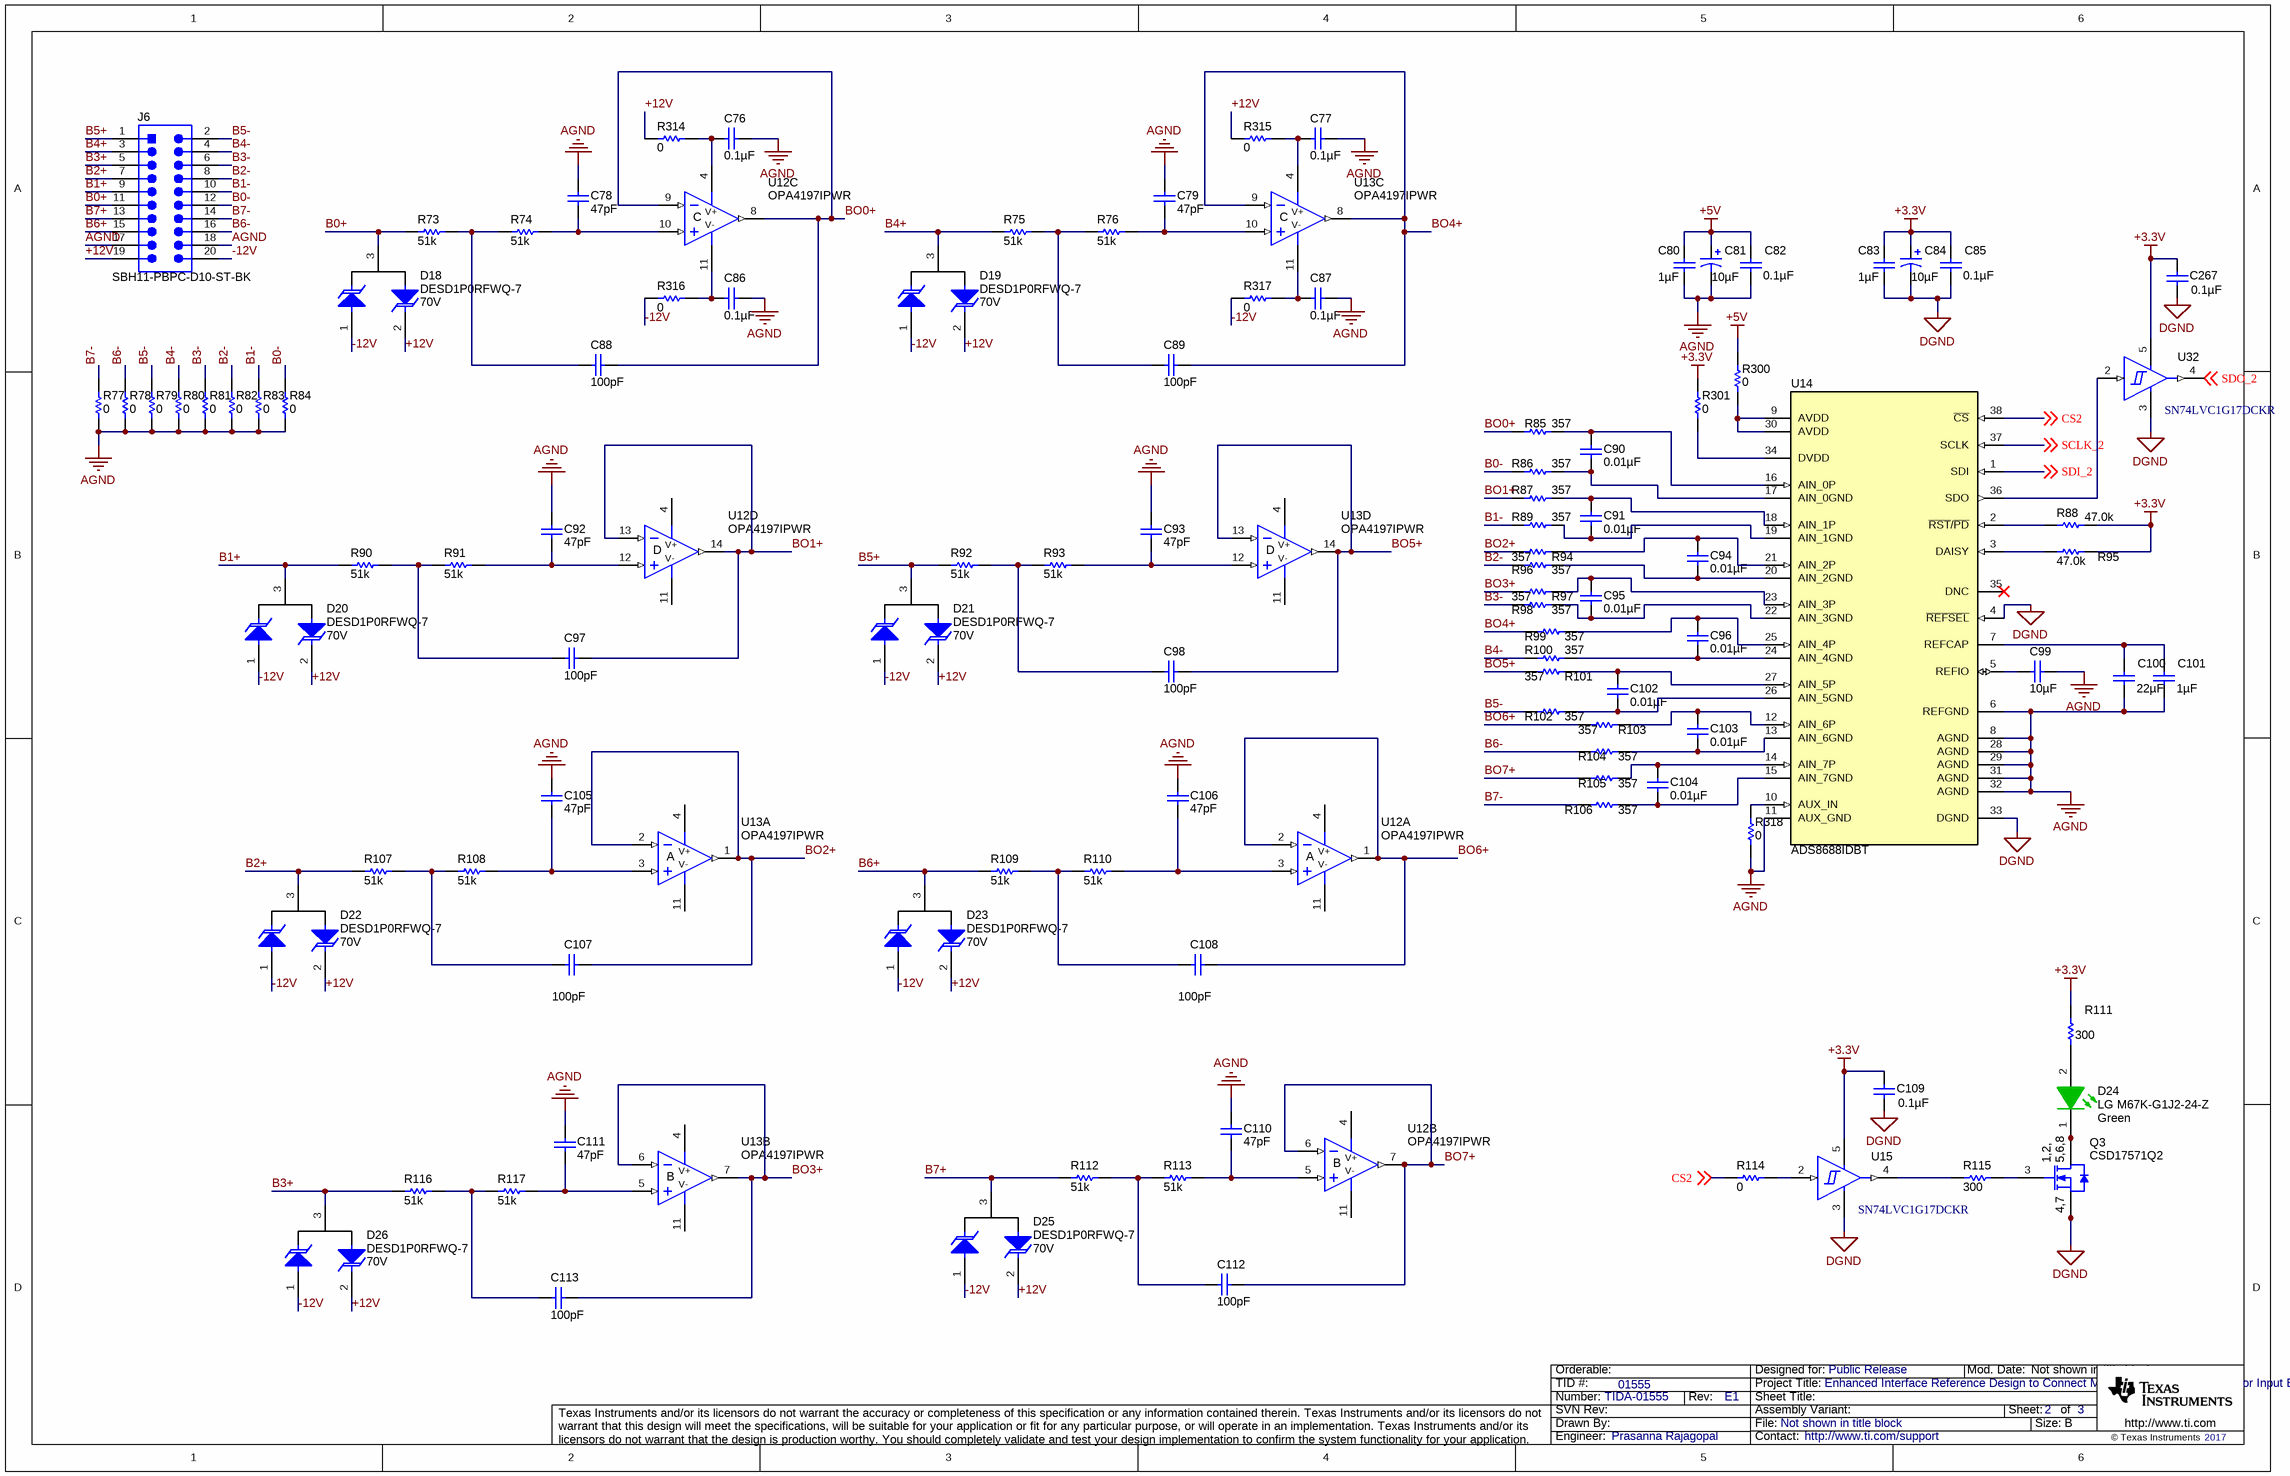
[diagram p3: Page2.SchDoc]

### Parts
C76  ValueDisplayed: 0.1µF  [0603]  (hidden comment: 06035C104KAT2A)
C77  ValueDisplayed: 0.1µF  [0603]  (hidden comment: 06035C104KAT2A)
C78  ValueDisplayed: 47pF  [0603]  (hidden comment: C0603C470J5GACTU)
C79  ValueDisplayed: 47pF  [0603]  (hidden comment: C0603C470J5GACTU)
C80  ValueDisplayed: 1µF  [0805_HV]  (hidden comment: LMK212B7105KD-T)
C81  ValueDisplayed: 10µF  [3216-18]  (hidden comment: TAJA106M010RNJ)
C82  ValueDisplayed: 0.1µF  [0402]  (hidden comment: C1005X5R1A104K050BA)
C83  ValueDisplayed: 1µF  [0805_HV]  (hidden comment: LMK212B7105KD-T)
C84  ValueDisplayed: 10µF  [3216-18]  (hidden comment: TAJA106M010RNJ)
C85  ValueDisplayed: 0.1µF  [0402]  (hidden comment: C1005X5R1A104K050BA)
C86  ValueDisplayed: 0.1µF  [0603]  (hidden comment: 06035C104KAT2A)
C87  ValueDisplayed: 0.1µF  [0603]  (hidden comment: 06035C104KAT2A)
C88  ValueDisplayed: 100pF  [0603]  (hidden comment: 06035A101FAT2A)
C89  ValueDisplayed: 100pF  [0603]  (hidden comment: 06035A101FAT2A)
C90  ValueDisplayed: 0.01µF  [0603]  (hidden comment: C1608X7R1H103K080AA)
C91  ValueDisplayed: 0.01µF  [0603]  (hidden comment: C1608X7R1H103K080AA)
C92  ValueDisplayed: 47pF  [0603]  (hidden comment: C0603C470J5GACTU)
C93  ValueDisplayed: 47pF  [0603]  (hidden comment: C0603C470J5GACTU)
C94  ValueDisplayed: 0.01µF  [0603]  (hidden comment: C1608X7R1H103K080AA)
C95  ValueDisplayed: 0.01µF  [0603]  (hidden comment: C1608X7R1H103K080AA)
C96  ValueDisplayed: 0.01µF  [0603]  (hidden comment: C1608X7R1H103K080AA)
C97  ValueDisplayed: 100pF  [0603]  (hidden comment: 06035A101FAT2A)
C98  ValueDisplayed: 100pF  [0603]  (hidden comment: 06035A101FAT2A)
C99  ValueDisplayed: 10µF  [0805_HV]  (hidden comment: GRM21BR71A106KE51L)
C100  ValueDisplayed: 22µF  [1210_280]  (hidden comment: C3225X7R1C226K250AC)
C101  ValueDisplayed: 1µF  [0603]  (hidden comment: C1608X7R1C105K080AC)
C102  ValueDisplayed: 0.01µF  [0603]  (hidden comment: C1608X7R1H103K080AA)
C103  ValueDisplayed: 0.01µF  [0603]  (hidden comment: C1608X7R1H103K080AA)
C104  ValueDisplayed: 0.01µF  [0603]  (hidden comment: C1608X7R1H103K080AA)
C105  ValueDisplayed: 47pF  [0603]  (hidden comment: C0603C470J5GACTU)
C106  ValueDisplayed: 47pF  [0603]  (hidden comment: C0603C470J5GACTU)
C107  ValueDisplayed: 100pF  [0603]  (hidden comment: 06035A101FAT2A)
C108  ValueDisplayed: 100pF  [0603]  (hidden comment: 06035A101FAT2A)
C109  ValueDisplayed: 0.1µF  [0603]  (hidden comment: GRM188R71C104KA01D)
C110  ValueDisplayed: 47pF  [0603]  (hidden comment: C0603C470J5GACTU)
C111  ValueDisplayed: 47pF  [0603]  (hidden comment: C0603C470J5GACTU)
C112  ValueDisplayed: 100pF  [0603]  (hidden comment: 06035A101FAT2A)
C113  ValueDisplayed: 100pF  [0603]  (hidden comment: 06035A101FAT2A)
C267  ValueDisplayed: 0.1µF  [0603]  (hidden comment: GRM188R71C104KA01D)
D18  DESD1P0RFWQ-7  value 70V  [SOT-323]
D19  DESD1P0RFWQ-7  value 70V  [SOT-323]
D20  DESD1P0RFWQ-7  value 70V  [SOT-323]
D21  DESD1P0RFWQ-7  value 70V  [SOT-323]
D22  DESD1P0RFWQ-7  value 70V  [SOT-323]
D23  DESD1P0RFWQ-7  value 70V  [SOT-323]
D24  LG M67K-G1J2-24-Z  value Green  [LG_M67K_Green]
D25  DESD1P0RFWQ-7  value 70V  [SOT-323]
D26  DESD1P0RFWQ-7  value 70V  [SOT-323]
J6  SBH11-PBPC-D10-ST-BK  [Sullins_SBH11-xxxC-D10-ST]
Q3  CSD17571Q2  [DQK0006C]
R73  ValueDisplayed: 51k  [0603]  (hidden comment: CRCW060351K0JNEA)
R74  ValueDisplayed: 51k  [0603]  (hidden comment: CRCW060351K0JNEA)
R75  ValueDisplayed: 51k  [0603]  (hidden comment: CRCW060351K0JNEA)
R76  ValueDisplayed: 51k  [0603]  (hidden comment: CRCW060351K0JNEA)
R77  ValueDisplayed: 0  [0603]  (hidden comment: CRCW06030000Z0EA)
R78  ValueDisplayed: 0  [0603]  (hidden comment: CRCW06030000Z0EA)
R79  ValueDisplayed: 0  [0603]  (hidden comment: CRCW06030000Z0EA)
R80  ValueDisplayed: 0  [0603]  (hidden comment: CRCW06030000Z0EA)
R81  ValueDisplayed: 0  [0603]  (hidden comment: CRCW06030000Z0EA)
R82  ValueDisplayed: 0  [0603]  (hidden comment: CRCW06030000Z0EA)
R83  ValueDisplayed: 0  [0603]  (hidden comment: CRCW06030000Z0EA)
R84  ValueDisplayed: 0  [0603]  (hidden comment: CRCW06030000Z0EA)
R85  ValueDisplayed: 357  [0402]  (hidden comment: CRCW0402357RFKED)
R86  ValueDisplayed: 357  [0402]  (hidden comment: CRCW0402357RFKED)
R87  ValueDisplayed: 357  [0402]  (hidden comment: CRCW0402357RFKED)
R88  ValueDisplayed: 47.0k  [0603]  (hidden comment: RC0603FR-0747KL)
R89  ValueDisplayed: 357  [0402]  (hidden comment: CRCW0402357RFKED)
R90  ValueDisplayed: 51k  [0603]  (hidden comment: CRCW060351K0JNEA)
R91  ValueDisplayed: 51k  [0603]  (hidden comment: CRCW060351K0JNEA)
R92  ValueDisplayed: 51k  [0603]  (hidden comment: CRCW060351K0JNEA)
R93  ValueDisplayed: 51k  [0603]  (hidden comment: CRCW060351K0JNEA)
R94  ValueDisplayed: 357  [0402]  (hidden comment: CRCW0402357RFKED)
R95  ValueDisplayed: 47.0k  [0603]  (hidden comment: RC0603FR-0747KL)
R96  ValueDisplayed: 357  [0402]  (hidden comment: CRCW0402357RFKED)
R97  ValueDisplayed: 357  [0402]  (hidden comment: CRCW0402357RFKED)
R98  ValueDisplayed: 357  [0402]  (hidden comment: CRCW0402357RFKED)
R99  ValueDisplayed: 357  [0402]  (hidden comment: CRCW0402357RFKED)
R100  ValueDisplayed: 357  [0402]  (hidden comment: CRCW0402357RFKED)
R101  ValueDisplayed: 357  [0402]  (hidden comment: CRCW0402357RFKED)
R102  ValueDisplayed: 357  [0402]  (hidden comment: CRCW0402357RFKED)
R103  ValueDisplayed: 357  [0402]  (hidden comment: CRCW0402357RFKED)
R104  ValueDisplayed: 357  [0402]  (hidden comment: CRCW0402357RFKED)
R105  ValueDisplayed: 357  [0402]  (hidden comment: CRCW0402357RFKED)
R106  ValueDisplayed: 357  [0402]  (hidden comment: CRCW0402357RFKED)
R107  ValueDisplayed: 51k  [0603]  (hidden comment: CRCW060351K0JNEA)
R108  ValueDisplayed: 51k  [0603]  (hidden comment: CRCW060351K0JNEA)
R109  ValueDisplayed: 51k  [0603]  (hidden comment: CRCW060351K0JNEA)
R110  ValueDisplayed: 51k  [0603]  (hidden comment: CRCW060351K0JNEA)
R111  ValueDisplayed: 300  [0603]  (hidden comment: CRCW0603300RJNEA)
R112  ValueDisplayed: 51k  [0603]  (hidden comment: CRCW060351K0JNEA)
R113  ValueDisplayed: 51k  [0603]  (hidden comment: CRCW060351K0JNEA)
R114  ValueDisplayed: 0  [0603]  (hidden comment: RMCF0603ZT0R00)
R115  ValueDisplayed: 300  [0603]  (hidden comment: CRCW0603300RJNEA)
R116  ValueDisplayed: 51k  [0603]  (hidden comment: CRCW060351K0JNEA)
R117  ValueDisplayed: 51k  [0603]  (hidden comment: CRCW060351K0JNEA)
R300  ValueDisplayed: 0  [0603]  (hidden comment: CRCW06030000Z0EA)
R301  ValueDisplayed: 0  [0603]  (hidden comment: CRCW06030000Z0EA)
R314  ValueDisplayed: 0  [0402]  (hidden comment: CRCW04020000Z0ED)
R315  ValueDisplayed: 0  [0402]  (hidden comment: CRCW04020000Z0ED)
R316  ValueDisplayed: 0  [0402]  (hidden comment: CRCW04020000Z0ED)
R317  ValueDisplayed: 0  [0402]  (hidden comment: CRCW04020000Z0ED)
R318  ValueDisplayed: 0  [0402]  (hidden comment: CRCW04020000Z0ED)
U12  OPA4197IPWR  [PW0014A_N]  (parts A,B,C,D of 4)
U13  OPA4197IPWR  [PW0014A_N]  (parts A,B,C,D of 4)
U14  ADS8688IDBT  [DBT0038A_N]
U15  SN74LVC1G17DCKR  [DCK0005A_N]
U32  SN74LVC1G17DCKR  [DCK0005A_N]

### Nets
+3.3V: C83.1 C84.1(+) C85.1 C109.1 C267.1 R88.2 R95.2 R111.2 R301.2 U15.5(VCC) U32.5(VCC)
+5V: C80.1 C81.1(+) C82.1 R300.2
+12V: D18.2(C) D19.2(C) D20.2(C) D21.2(C) D22.2(C) D23.2(C) D25.2(C) D26.2(C) J6.19 R314.1 R315.1
-12V: D18.1(A) D19.1(A) D20.1(A) D21.1(A) D22.1(A) D23.1(A) D25.1(A) D26.1(A) J6.20 R316.1 R317.1
AGND: C76.1 C77.1 C78.1 C79.1 C80.2 C81.2(-) C82.2 C86.1 C87.1 C92.1 C93.1 C99.2 C100.2 C101.2 C105.1 C106.1 C110.1 C111.1 J6.17 J6.18 R77.1 R78.1 R79.1 R80.1 R81.1 R82.1 R83.1 R84.1 R318.1 U14.6(REFGND) U14.8(AGND) U14.11(AUX_GND) U14.28(AGND) U14.29(AGND) U14.31(AGND) U14.32(AGND)
DGND: C83.2 C84.2(-) C85.2 C109.2 C267.2 Q3.4(S) Q3.7(S) U14.4(~{REFSEL}) U14.33(DGND) U15.3(GND) U32.3(GND)
B0+: D18.3(C) J6.11 R73.1
B0-: J6.12 R84.2 R86.1
B1+: D20.3(C) J6.9 R90.1
B1-: J6.10 R83.2 R89.1
B2+: D22.3(C) J6.7 R107.1
B2-: J6.8 R82.2 R96.1
B3+: D26.3(C) J6.5 R116.1
B3-: J6.6 R81.2 R98.1
B4+: D19.3(C) J6.3 R75.1
B4-: J6.4 R80.2 R100.1
B5+: D21.3(C) J6.1 R92.1
B5-: J6.2 R79.2 R102.1
B6+: D23.3(C) J6.15 R109.1
B6-: J6.16 R78.2 R104.1
B7+: D25.3(C) J6.13 R112.1
B7-: J6.14 R77.2 R106.1
BO0+: C88.1 R85.1 U12.8(OUT) U12.9(IN-)
BO1+: C97.1 R87.1 U12.13(IN-) U12.14(OUT)
BO2+: C107.1 R94.1 U13.1(OUT) U13.2(IN-)
BO3+: C113.1 R97.1 U13.6(IN-) U13.7(OUT)
BO4+: C89.1 R99.1 U13.8(OUT) U13.9(IN-)
BO5+: C98.1 R101.1 U13.13(IN-) U13.14(OUT)
BO6+: C108.1 R103.1 U12.1(OUT) U12.2(IN-)
BO7+: C112.1 R105.1 U12.6(IN-) U12.7(OUT)
CS2: R114.1 U14.38(~{CS}) ; off-sheet CS2
SCLK_2: U14.37(SCLK) ; off-sheet SCLK_2
SDI_2: U14.1(SDI) ; off-sheet SDI_2
SDO_2: U32.4(Y) ; off-sheet SDO_2
NetC76_2: C76.2 R314.2 U12.4(V+)
NetC77_2: C77.2 R315.2 U13.4(V+)
NetC78_2: C78.2 R74.2 U12.10(IN+)
NetC79_2: C79.2 R76.2 U13.10(IN+)
NetC86_2: C86.2 R316.2 U12.11(V-)
NetC87_2: C87.2 R317.2 U13.11(V-)
NetC88_2: C88.2 R73.2 R74.1
NetC89_2: C89.2 R75.2 R76.1
NetC90_1: C90.1 R85.2 U14.16(AIN_0P)
NetC90_2: C90.2 R86.2 U14.17(AIN_0GND)
NetC91_1: C91.1 R87.2 U14.18(AIN_1P)
NetC91_2: C91.2 R89.2 U14.19(AIN_1GND)
NetC92_2: C92.2 R91.2 U12.12(IN+)
NetC93_2: C93.2 R93.2 U13.12(IN+)
NetC94_1: C94.1 R94.2 U14.21(AIN_2P)
NetC94_2: C94.2 R96.2 U14.20(AIN_2GND)
NetC95_1: C95.1 R97.2 U14.23(AIN_3P)
NetC95_2: C95.2 R98.2 U14.22(AIN_3GND)
NetC96_1: C96.1 R99.2 U14.25(AIN_4P)
NetC96_2: C96.2 R100.2 U14.24(AIN_4GND)
NetC97_2: C97.2 R90.2 R91.1
NetC98_2: C98.2 R92.2 R93.1
NetC99_1: C99.1 U14.5(REFIO)
NetC100_1: C100.1 C101.1 U14.7(REFCAP)
NetC102_1: C102.1 R101.2 U14.27(AIN_5P)
NetC102_2: C102.2 R102.2 U14.26(AIN_5GND)
NetC103_1: C103.1 R103.2 U14.12(AIN_6P)
NetC103_2: C103.2 R104.2 U14.13(AIN_6GND)
NetC104_1: C104.1 R105.2 U14.14(AIN_7P)
NetC104_2: C104.2 R106.2 U14.15(AIN_7GND)
NetC105_2: C105.2 R108.2 U13.3(IN+)
NetC106_2: C106.2 R110.2 U12.3(IN+)
NetC107_2: C107.2 R107.2 R108.1
NetC108_2: C108.2 R109.2 R110.1
NetC110_2: C110.2 R113.2 U12.5(IN+)
NetC111_2: C111.2 R117.2 U13.5(IN+)
NetC112_2: C112.2 R112.2 R113.1
NetC113_2: C113.2 R116.2 R117.1
NetD24_1: D24.1(K) Q3.1(D) Q3.2(D) Q3.5(D) Q3.6(D) Q3.8(D)
NetD24_2: D24.2(A) R111.1
NetQ3_3: Q3.3(G) R115.1
NetR88_1: R88.1 U14.2(~{RST}/~{PD})
NetR95_1: R95.1 U14.3(DAISY)
NetR114_2: R114.2 U15.2(A)
NetR115_2: R115.2 U15.4(Y)
NetR300_1: R300.1 U14.9(AVDD) U14.30(AVDD)
NetR301_1: R301.1 U14.34(DVDD)
NetR318_2: R318.2 U14.10(AUX_IN)
NetU14_36: U14.36(SDO) U32.2(A)

Not connected (* = marked no-connect by the designer): U14 35(DNC)*

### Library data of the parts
C76 C77 C86 C87 = 06035C104KAT2A: as C1 on sheet Page1
C78 C79 C92 C93 C105 C106 C110 C111 = C0603C470J5GACTU: as C3 on sheet Page1
C80 C83 = LMK212B7105KD-T: as C5 on sheet Page1
C81 C84 = TAJA106M010RNJ: as C6 on sheet Page1
C82 C85 = C1005X5R1A104K050BA: as C7 on sheet Page1
C88 C89 C97 C98 C107 C108 C112 C113 = 06035A101FAT2A: as C13 on sheet Page1
C90 C91 C94-C96 C102-C104 = C1608X7R1H103K080AA: as C15 on sheet Page1
C99 = GRM21BR71A106KE51L: as C24 on sheet Page1
C100 = C3225X7R1C226K250AC: as C25 on sheet Page1
C101 = C1608X7R1C105K080AC: as C26 on sheet Page1
C109 C267 = GRM188R71C104KA01D: as C34 on sheet Page1
D18-D23 D25 D26 = DESD1P0RFWQ-7: as D1 on sheet Page1
D24 = LG M67K-G1J2-24-Z: as D7 on sheet Page1
J6 = SBH11-PBPC-D10-ST-BK: as J1 on sheet Page1
Q3 = CSD17571Q2: as Q1 on sheet Page1
R73-R76 R90-R93 R107-R110 R112 R113 R116 R117 = CRCW060351K0JNEA: as R1 on sheet Page1
R77-R84 R300 R301 = CRCW06030000Z0EA: as R5 on sheet Page1
R85-R87 R89 R94 R96-R106 = CRCW0402357RFKED: as R13 on sheet Page1
R88 R95 = RC0603FR-0747KL: as R16 on sheet Page1
R111 R115 = CRCW0603300RJNEA: as R39 on sheet Page1
R114 = RMCF0603ZT0R00: as R42 on sheet Page1
R314-R318 = CRCW04020000Z0ED: as R69 on sheet Page1
U12 U13 = OPA4197IPWR: as U1 on sheet Page1
U14 = ADS8688IDBT: as U3 on sheet Page1
U15 U32 = SN74LVC1G17DCKR: as U4 on sheet Page1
